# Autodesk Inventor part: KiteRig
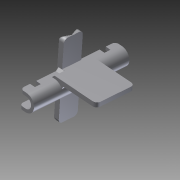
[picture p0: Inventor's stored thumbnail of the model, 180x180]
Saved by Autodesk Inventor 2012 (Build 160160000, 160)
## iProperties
Created: 2013-06
Part Number: KiteRig
Material: Default
Document SubType Name: Modeling
Designer: Norm
Density: 1 g/cm^3
Author: Norm
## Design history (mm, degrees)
sketch "Sketch1"
  geometry: L1 (5.715, 0)-(5.715, -5.715); L2 (5.715, -5.715)-(-5.715, -5.715); L3 (-5.715, -5.715)-(-5.715, 0); A1 r 5.715 centre (0, 0) between (5.715, 0) and (-5.715, 0); 1 further point
  constraints: 6 end point, 2 point on circle, 1 centre point, 1 coincident, 1 parallel
  dimensions: "d0" = 11.43 diameter of A1; "d5" = 5.715 distance of L1.start L1.end (= 0.5 x d0)
extrude "Extrusion1" new body sketch "Sketch1" stored distance "d1" = 63.5; taper "d2" = 0 deg
workplane "Work Plane1"
sketch "Sketch3"
  geometry: L1 (-5.715, 5.715)-(5.715, 5.715) reference; L2 (3.619, 0)-(3.619, 5.715); L3 (3.619, 5.715)-(-3.62, 5.715); L4 (-3.62, 5.715)-(-3.619, 0); A1 r 5.715 centre (0, 0) between (-5.715, 0) and (5.715, 0) reference; A2 r 3.619 centre (0, 0) between (-3.619, 0) and (3.619, 0)
  constraints: 6 end point, 2 point on circle, 1 centre point, 1 coincident, 1 parallel, 1 point on line
extrude "Extrusion2" cut sketch "Sketch3" stored distance "d7" = 63.5; taper "d8" = 0 deg
sketch "Sketch6"
  geometry: 2 further points
  constraints: 1 coincident
workplane "Work Plane2"
sketch "Sketch8"
  geometry: L1 (4.648, 0)-(4.665, 0); L2 (4.665, 0)-(4.665, 6.007); L3 (4.665, 6.007)-(-4.648, 6.007); L4 (-4.648, 6.007)-(-4.648, 0); A1 r 4.648 centre (0, 0) between (-4.648, 0) and (4.648, 0); 1 further point
  constraints: 8 end point, 2 parallel, 2 point on circle, 1 centre point, 1 coincident, 1 horizontal, 1 perpendicular
  dimensions: "d16" = 9.2964 diameter of A1
extrude "Extrusion5" cut sketch "Sketch8" stored distance "d17" = 17.145; taper "d18" = 0 deg
sketch "Sketch9"
  geometry: L1 (-4.648, 6.35)-(-7.188, 6.35); L2 (-7.188, -6.35)-(-4.648, -6.35); L3 (-7.188, 6.35)-(-4.648, 0); L4 (-7.188, -6.35)-(-4.648, 0); L5 (-4.648, 6.35)-(-2.108, 6.35); L6 (-2.108, 6.35)-(-2.108, -6.35); L7 (-2.108, -6.35)-(-4.648, -6.35); L8 (-4.648, 6.35)-(-7.188, 6.35); L9 (-7.188, -6.35)-(-4.648, -6.35); L10 (-7.188, 6.35)-(-4.648, 0); L11 (-7.188, -6.35)-(-4.648, 0); L12 (-4.648, 6.35)-(-2.108, 6.35); L13 (-2.108, 6.35)-(-2.108, -6.35); L14 (-2.108, -6.35)-(-4.648, -6.35); 1 further point
  constraints: 28 end point, 4 horizontal, 4 parallel, 2 perpendicular
sketch "Sketch10"
  geometry: L1 (-2.115, 6.327)-(-7.185, 6.327); L2 (-7.185, 6.327)-(-7.185, -6.364); L3 (-7.185, -6.364)-(-2.115, -6.364); L4 (-2.115, -6.364)-(-2.115, 6.327); 1 further point
  constraints: 8 end point, 2 parallel, 1 horizontal, 1 perpendicular
extrude "Extrusion6" join sketch "Sketch10" stored distance "d27" = 50.8; taper "d28" = 0 deg
sketch "Sketch11" dims "d29" = 9.2964
  geometry: L1 (6.364, -7.185)-(-6.327, -7.185) reference; L2 (-6.327, -7.185)-(0, -4.648); L3 (6.364, -7.185)-(0, -4.648); 2 further points
  constraints: 4 end point, 1 coincident, 1 vertical alignment, 2 other
extrude "Extrusion7" cut sketch "Sketch11" stored distance "d30" = 50.8; taper "d31" = 0 deg
sketch "Sketch12"
  geometry: L1 (4.64, 8.553)-(-4.623, 8.553); L2 (-4.623, 8.553)-(-4.623, -8.585); L3 (-4.623, -8.585)-(4.64, -8.585); L4 (4.64, -8.585)-(4.64, 8.553); 1 further point
  constraints: 8 end point, 2 parallel, 1 horizontal, 1 perpendicular
extrude "Extrusion8" cut sketch "Sketch12" distance "d32" = 50.8; taper "d33" = 0 deg
sketch "Sketch13"
  geometry: L1 (-6.327, -7.185)-(0, -4.648) reference; L2 (0, -4.648)-(6.364, -7.185) reference; L3 (6.364, -2.115)-(6.364, -7.185) reference; L4 (-6.327, -7.185)-(-6.327, -2.115) reference; L5 (-6.327, -6.657)-(0, -4.12); L6 (0, -4.12)-(6.364, -6.657); 1 further point
  constraints: 4 end point, 2 parallel, 2 point on line
extrude "Extrusion9" cut sketch "Sketch13" stored distance "d34" = 50.8; taper "d35" = 0 deg
sketch "Sketch17"
  geometry: L1 (-25.386, 3.6)-(-25.386, 0) reference; L2 (-63.5, 5.715)-(-63.5, 0) reference; L3 (-63.5, 1.062)-(-38.077, 1.062); L4 (-38.077, 1.062)-(-38.077, 0); L5 (-38.077, 0)-(-63.5, 0); L6 (-63.5, 0)-(-63.5, 1.062); L7 (-25.386, 1.062)-(0, 1.062); L8 (0, 1.062)-(0, 0); L9 (0, 0)-(-25.386, 0); L10 (-25.386, 0)-(-25.386, 1.062); 1 further point
  constraints: 16 end point, 4 parallel, 2 horizontal, 2 perpendicular, 2 point on line
extrude "Extrusion11" cut sketch "Sketch17" stored distance "d38" = 50.8; taper "d39" = 0 deg
sketch "Sketch21"
  geometry: L1 (17.918, -19.242)-(20.874, -19.242); L2 (20.874, -19.242)-(20.874, 6.342); L3 (20.874, 6.342)-(17.918, 6.342); L4 (17.918, 6.342)-(17.918, -19.242); 1 further point
  constraints: 8 end point, 2 parallel, 1 horizontal, 1 perpendicular
extrude "Extrusion12" join sketch "Sketch21" distance "d40" = 31.75; taper "d41" = 0 deg
sketch "Sketch25"
  geometry: L1 (-25.423, 0)-(0, 0) reference; L2 (-10.584, 0)-(-6.57, 0); L3 (-6.57, 0)-(-6.57, 3.457); L4 (-6.57, 3.457)-(-10.584, 3.457); L5 (-10.584, 3.457)-(-10.584, 0); L6 (-31.75, 7.808)-(-31.75, -17.195); L7 (-52.916, 0)-(-56.93, 0); L8 (-56.93, 0)-(-56.93, 3.457); L9 (-56.93, 3.457)-(-52.916, 3.457); L10 (-52.916, 3.457)-(-52.916, 0); 1 further point
  constraints: 18 end point, 4 symmetric about line, 3 parallel, 1 horizontal, 1 perpendicular, 1 point on line
extrude "Extrusion14" cut sketch "Sketch25" distance "d44" = 25.4; taper "d45" = 0 deg
chamfer "Chamfer1" distance "d46" = 1.651; stored, may be unused: second distance "d47" = 3.175, angle "d48" = 45 deg
chamfer "Chamfer2" distance "d49" = 1.651; stored, may be unused: second distance "d50" = 3.175, angle "d51" = 45 deg
chamfer "Chamfer3" distance "d52" = 1.651; stored, may be unused: second distance "d53" = 3.175, angle "d54" = 45 deg
chamfer "Chamfer4" distance "d55" = 2.54; stored, may be unused: second distance "d56" = 3.175, angle "d57" = 45 deg
fillet "Fillet1" dims "d58" = 1.016
fillet "Fillet2" dims "d59" = 2.54
fillet "Fillet3" dims "d60" = 2.54
fillet "Fillet4" dims "d61" = 2.54
body "Solid1"
